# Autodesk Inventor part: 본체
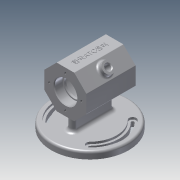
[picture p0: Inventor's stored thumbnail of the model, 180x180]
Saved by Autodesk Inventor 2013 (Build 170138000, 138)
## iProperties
Created: 2017-06
Part Number: 본체
Material: 알루미늄 6061
Document SubType Name: Modeling
Designer: Administrator
Density: 2.71 g/cm^3
Mass: 562.523 g
Surface Area: 565.555 cm^2
Volume: 207.573 cm^3
Author: Administrator
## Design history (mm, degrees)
sketch "스케치1"
  geometry: L1 (30, -12.426)-(12.426, -30); L2 (12.426, -30)-(-12.426, -30); L3 (-12.426, -30)-(-30, -12.426); L4 (-30, -12.426)-(-30, 12.426); L5 (-30, 12.426)-(-12.426, 30); L6 (-12.426, 30)-(12.426, 30); L7 (12.426, 30)-(30, 12.426); L8 (30, 12.426)-(30, -12.426); 2 further points
  constraints: 16 end point, 1 coincident, 17 other
  dimensions: "d0" = 30 distance from line of point (0, 0) L8
extrude "돌출1" new body sketch "스케치1" stored distance "d1" = 70; taper "d2" = 0 deg
sketch "스케치2"
  geometry: L1 (-35, -30)-(-35, 30) reference; L2 (-35, 30)-(35, 30) reference; L3 (35, 30)-(35, -30) reference; L4 (35, -30)-(-35, -30) reference; L5 (-35, 0)-(35, 0); L6 (-35, 16)-(-23, 16); L7 (-23, 16)-(-23, 14); L8 (-23, 14)-(-20, 14); L9 (-20, 14)-(-20, 25); L10 (-20, 25)-(20, 25); L11 (20, 25)-(20, 14); L12 (20, 14)-(23, 14); L13 (23, 14)-(23, 16); L14 (23, 16)-(35, 16); L15 (-35, 16)-(-35, 0); L16 (35, 16)-(35, 0); 1 further point
  constraints: 24 end point, 7 parallel, 4 perpendicular, 2 midpoint, 2 point on line
  dimensions: "d3" = 32 diameter of L6 L5; "d5" = 28 diameter of L8 L5; "d6" = 50 diameter of L10 L5; "d7" = 28 diameter of L12 L5; "d8" = 32 diameter of L14 L5; "d9" = 40 distance of L9.end L10.end; "d10" = 12 distance of L6.start L6.end; "d11" = 12 distance of L13.end L14.end; "d12" = 3 distance of L7.end L8.end
revolve "회전1" sketch "스케치2" stored, may be unused: angle "d13" = 90 deg
node "작업 평면1"
sketch "스케치3"
  geometry: C1 r 55 at (0, 0); 1 further point
  constraints: 1 centre point, 1 coincident
  dimensions: "d15" = 110 diameter of C1
extrude "돌출2" join sketch "스케치3" distance "d16" = 10; taper "d17" = 0 deg
sketch "스케치4"
  geometry: L1 (0, 0)-(0, 55); L2 (0, 0)-(0, -55); L3 (0, 0)-(-38.891, 38.891); L4 (0, 0)-(38.891, -38.891); L5 (0, 0)-(-38.891, -38.891); L6 (0, 0)-(38.891, 38.891); L7 (0, 0)-(-55, 0); L8 (0, 0)-(55, 0); A1 r 43 centre (0, 0) between (-30.406, 30.406) and (30.406, 30.406); A2 r 5 centre (-30.406, 30.406) between (-33.941, 33.941) and (-26.87, 26.87); A3 r 5 centre (30.406, -30.406) between (33.941, -33.941) and (26.87, -26.87); A4 r 5 centre (-30.406, -30.406) between (-26.87, -26.87) and (-33.941, -33.941); A5 r 38 centre (0, 0) between (-26.87, -26.87) and (26.87, -26.87); A6 r 38 centre (0, 0) between (26.87, 26.87) and (-26.87, 26.87); A7 r 48 centre (0, 0) between (-33.941, -33.941) and (33.941, -33.941); A8 r 48 centre (0, 0) between (33.941, 33.941) and (-33.941, 33.941); A9 r 2 centre (-30.406, 30.406) between (-31.82, 31.82) and (-28.991, 28.991); A10 r 2 centre (30.406, 30.406) between (28.991, 28.991) and (31.82, 31.82); A11 r 2 centre (30.406, -30.406) between (31.82, -31.82) and (28.991, -28.991); A12 r 2 centre (-30.406, -30.406) between (-28.991, -28.991) and (-31.82, -31.82); A13 r 45 centre (0, 0) between (31.82, 31.82) and (-31.82, 31.82); A14 r 41 centre (0, 0) between (28.991, 28.991) and (-28.991, 28.991); A15 r 41 centre (0, 0) between (-28.991, -28.991) and (28.991, -28.991); A16 r 45 centre (0, 0) between (-31.82, -31.82) and (31.82, -31.82); A17 r 5 centre (30.406, 30.406) between (26.87, 26.87) and (33.941, 33.941); 1 further point
  constraints: 36 point on circle, 17 centre point, 16 end point, 11 coincident, 9 point on line, 4 tangent, 2 collinear, 1 perpendicular, 1 vertical, 9 other
  dimensions: "d19" = 86 diameter of A1; "d21" = 45 deg angle of L3 L7; "d22" = 45 deg angle of L8 L6; "d23" = 45 deg angle of L5 L7; "d24" = 45 deg angle of L8 L4; "d25" = 10 diameter of A2; "d27" = 10 diameter of A3; "d28" = 10 diameter of A4; "d29" = 4 diameter of A9; "d30" = 4 diameter of A10; "d31" = 4 diameter of A11; "d32" = 4 diameter of A12
extrude "돌출3" cut sketch "스케치4" distance "d33" = 3; taper "d34" = 0 deg
extrude "돌출4" cut sketch "스케치4" stored distance "d35" = 3; taper "d36" = 0 deg
sketch "스케치5"
  geometry: L1 (-24, -5)-(24, -5); L2 (24, -5)-(24, 5); L3 (24, 5)-(-24, 5); L4 (-24, 5)-(-24, -5); L5 (-24, -5)-(24, 5); L6 (24, -5)-(-24, 5); C1 r 55 at (0, 0) reference; C2 r 5 at (24, 0); C3 r 5 at (-24, 0)
  constraints: 12 end point, 4 midpoint, 2 centre point, 2 parallel, 1 horizontal, 1 perpendicular
  dimensions: "d37" = 48 distance of L3.end L2.end; "d38" = 10 distance of L2.end L1.end; "d40" = 10 diameter of C2; "d41" = 10 diameter of C3
extrude "돌출5" join sketch "스케치5" stored distance "d42" = 3; taper "d43" = 0 deg
sketch "스케치6" dims "d44" = 46
  geometry: C1 r 16 at (0, 0) reference; 2 further points
  constraints: 2 horizontal alignment, 1 coincident, 2 other
hole "구멍1" sketch "스케치6" at (23, 0) diameter "d45" = 3.242; stored, may be unused: countersink angle "d49" = 90 deg, drill point angle "d51" = 118 deg; dims "d46" = 8, "d47" = 4, "d48" = 2, "d50" = 10
sketch "스케치7"
  geometry: C1 r 8 at (35, 12.426); 1 further point
  constraints: 1 centre point, 1 coincident
  dimensions: "d55" = 16 diameter of C1
extrude "돌출6" join sketch "스케치7" distance "d56" = 7; taper "d57" = 0 deg
sketch "스케치8"
  geometry: C1 r 8 at (0, 0) reference
hole "구멍2" sketch "스케치8" at (0, 0) diameter "d58" = 8; stored, may be unused: countersink angle "d62" = 90 deg, drill point angle "d64" = 0 deg; dims "d59" = 8, "d60" = 4, "d61" = 2, "d63" = 10
sketch "스케치9"
  geometry: L1 (0, 0)-(0, 24.853) reference; L2 (70, 42.426)-(0, 42.426) reference; 2 further points
  constraints: 1 other
  dimensions: "d66" = 30 distance from line of L2 point (35, 12.426); "d67" = 35 distance from line of L1 point (35, 12.426)
feature "엠보싱1" sketch "스케치9" dims "d3" = 32, "d5" = 28, "d6" = 50, "d7" = 28, "d8" = 32, "d9" = 40, "d10" = 12, "d11" = 12, "d12" = 3, "d68" = 0.5, "d69" = 0
fillet "모깎기1" dims "d70" = 3
fillet "모깎기2" dims "d71" = 5
fillet "모깎기3" dims "d72" = 1
fillet "모깎기4" dims "d73" = 3
chamfer "모따기1" distance "d74" = 1; stored, may be unused: second distance "d75" = 2, angle "d76" = 45 deg
fillet "모깎기5" dims "d77" = 0.3
fillet "모깎기6" dims "d78" = 3
node "솔리드1"
pattern_circular "원형 패턴1" dims angle "d53" = 360 deg
mirror "대칭1"
node "절단 모서리 투영1"
other parameters: "d14" = -62, "d18" = 96, "d20" = 76
